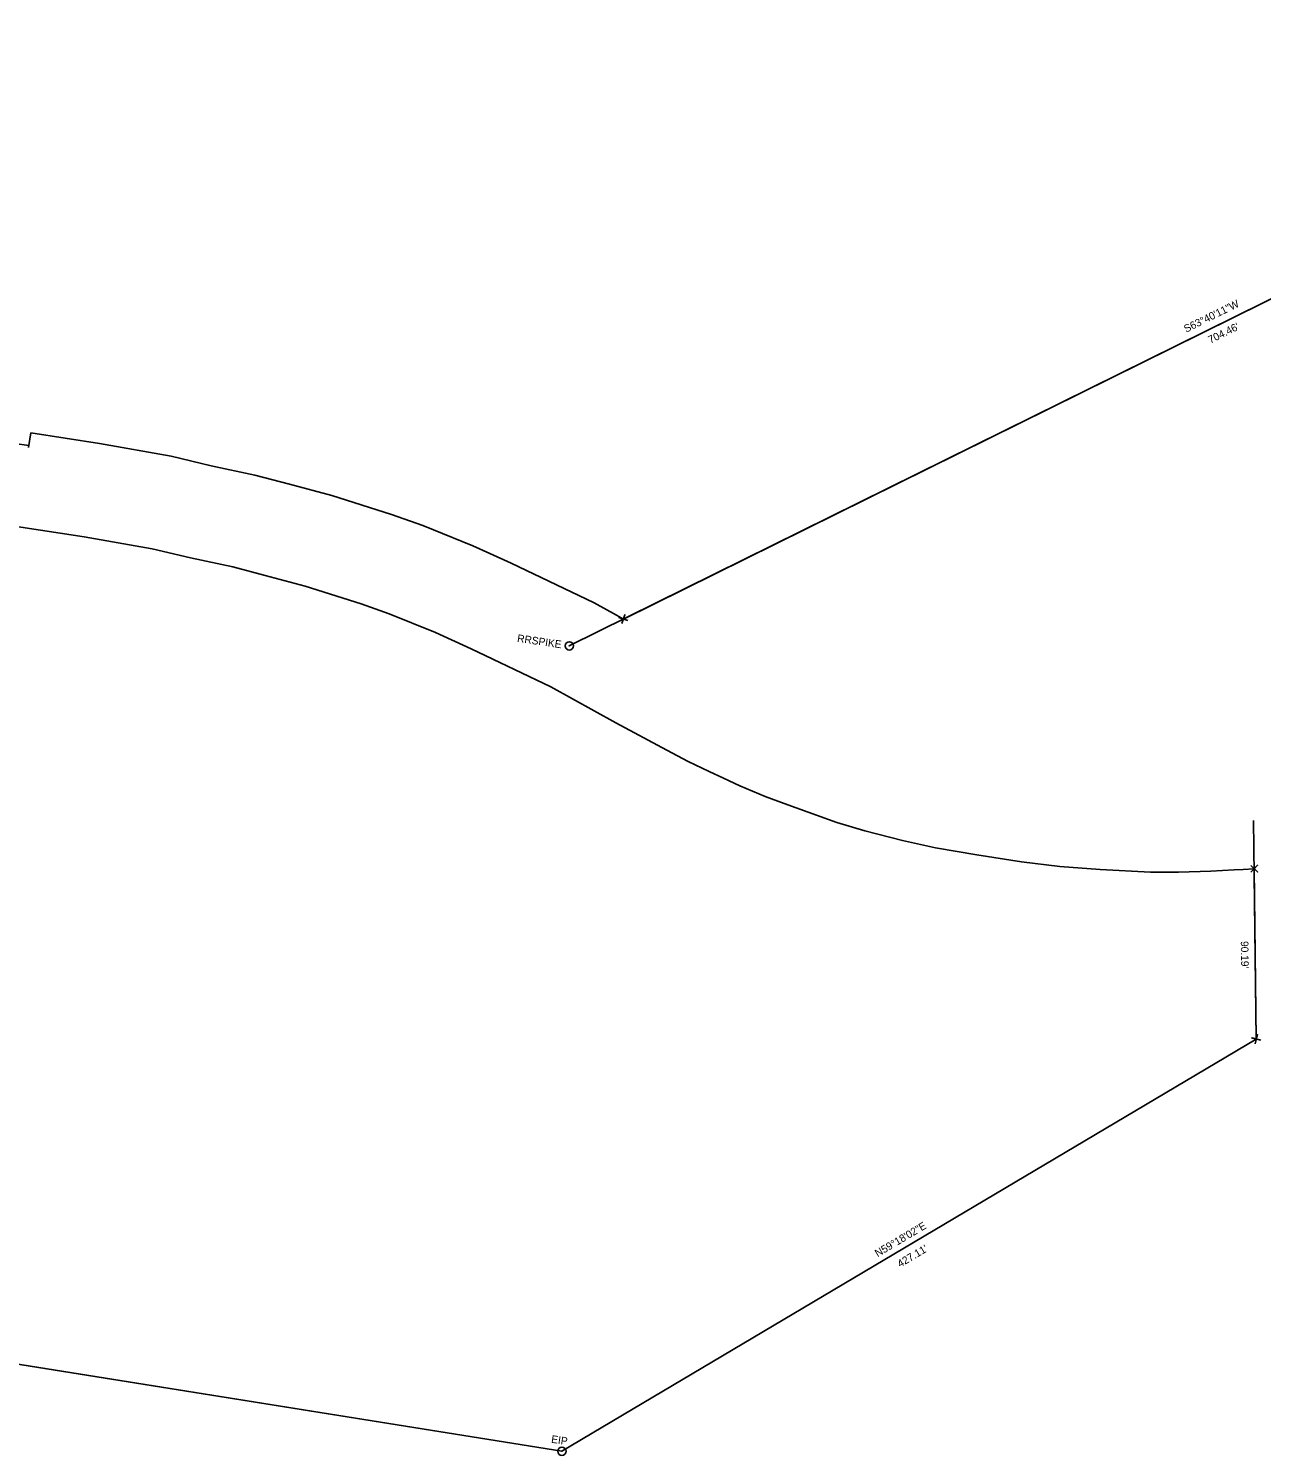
# Model space of a CAD drawing. Extents: x 1107874 to 1110849, y 645477 to 647181.
# Drawn here: x 1109568 to 1110220, y 645884 to 646639 of the extents above; entities that cross this region are included whole.
import ezdxf

# ---------------------------------------------------------------- set-up
doc = ezdxf.new("R2010")
doc.units = 0
for name, color, linetype in [('Exist Property Corner CELL', 7, 'Continuous'), ('Exist Property Iron Pin CELL', 7, 'Continuous'), ('Exist Property Line', 7, 'Continuous'), ('Exist Property Text', 7, 'Continuous'), ('Exist Right of Way Line', 7, 'Continuous')]:
    doc.layers.add(name, color=color, linetype=linetype)

msp = doc.modelspace()

# ---------------------------------------------------------------- linework, layer by layer
at = {"layer": 'Exist Property Corner CELL'}
for p, q in [((1109882.58, 646326.39), (1109882.58, 646326.39)), ((1110216.16, 646194.36), (1110216.16, 646194.36)), ((1110217.27, 646104.18), (1110217.27, 646104.18))]:
    msp.add_line(p, q, dxfattribs=at)
for points in [[(1109881.78, 646324.02), (1109883.38, 646328.75), (1109882.58, 646326.39), (1109880.21, 646327.19), (1109884.94, 646325.59)], [(1110214.37, 646196.11), (1110217.95, 646192.62), (1110216.16, 646194.36), (1110217.9, 646196.15), (1110214.41, 646192.58)], [(1110216.66, 646101.76), (1110217.89, 646106.61), (1110217.27, 646104.18), (1110214.85, 646104.8), (1110219.7, 646103.57)]]:
    msp.add_lwpolyline(points, dxfattribs=at)
at = {"layer": 'Exist Property Iron Pin CELL'}
for centre, radius in [((1109853.98, 646312.24), 2.2), ((1109853.98, 646312.24), 0.0707), ((1109850.02, 645886.13), 2.2), ((1109850.02, 645886.13), 0.0707)]:
    msp.add_circle(centre, radius, dxfattribs=at)
at = {"layer": 'Exist Property Line'}
for p, q in [((1110513.95, 646638.85), (1109853.98, 646312.24)), ((1110513.95, 646638.85), (1109882.58, 646326.39)), ((1110217.27, 646104.18), (1110215.84, 646219.83)), ((1110217.27, 646104.18), (1110216.16, 646194.36)), ((1109850.02, 645886.13), (1110217.27, 646104.18)), ((1109185.59, 645992.53), (1109850.02, 645886.13)), ((1109193.36, 645991.28), (1109850.02, 645886.13))]:
    msp.add_line(p, q, dxfattribs=at)
at = {"layer": 'Exist Right of Way Line'}
for p, q in [((1109568.01, 646417.2), (1109569.19, 646424.89)), ((1109882.58, 646326.39), (1109878.93, 646328.41))]:
    msp.add_line(p, q, dxfattribs=at)
for points in [[(1109878.93, 646328.41), (1109867.12, 646334.97), (1109823.18, 646356), (1109811.98, 646361.11), (1109802.94, 646365.24), (1109776.44, 646375.92), (1109759.94, 646381.82), (1109728.36, 646391.8), (1109706.02, 646397.77), (1109687.68, 646402.62), (1109664.63, 646407.57), (1109643.46, 646412.56), (1109605.52, 646419.3), (1109569.19, 646424.89)], [(1109561.58, 646375.47), (1109597.34, 646369.97), (1109633.35, 646363.57), (1109653.65, 646358.79), (1109676.03, 646353.98), (1109693.17, 646349.45), (1109714.37, 646343.78), (1109743.98, 646334.43), (1109758.67, 646329.17), (1109783.19, 646319.29), (1109802, 646310.7), (1109844.17, 646290.52), (1109878.49, 646271.46), (1109905.55, 646257), (1109916.88, 646251.09), (1109927.95, 646245.84), (1109935.44, 646242.24), (1109944.11, 646238.21), (1109957.51, 646232.61), (1109969.44, 646228.07), (1109995.47, 646218.72), (1110010.25, 646214.36), (1110030.19, 646209.25), (1110047.59, 646205.48), (1110069.4, 646201.72), (1110093.05, 646197.93), (1110113.4, 646195.56), (1110134.76, 646193.9), (1110161.35, 646192.54), (1110176.04, 646192.54), (1110193.17, 646193.03), (1110205.47, 646193.72)], [(1110205.47, 646193.72), (1110210.32, 646193.99), (1110216.16, 646194.36)]]:
    msp.add_lwpolyline(points, dxfattribs=at)
msp.add_arc((1108042.08, 636517.61), 10017.5, 81.23737, 82.647299, dxfattribs=at)

# ---------------------------------------------------------------- texts
at = {"layer": 'Exist Property Text'}
for s, rotation, p in [('S63°40\'11"W', 26.33025, (1110180.17, 646477.88)), ("704.46'", 26.33025, (1110192.99, 646472.09)), ('RRSPIKE', 351.59957, (1109826.2, 646314.41)), ("90.19'", 270.71059, (1110209.07, 646156.06)), ('N59°18\'02"E', 30.69948, (1110017.01, 645988.77)), ("427.11'", 30.69948, (1110028.91, 645983.27)), ('EIP', 351.59957, (1109844.2, 645890.7))]:
    msp.add_text(s, height=4.02, rotation=rotation, dxfattribs=at).set_placement(p)

doc.saveas('drawing.dxf')
